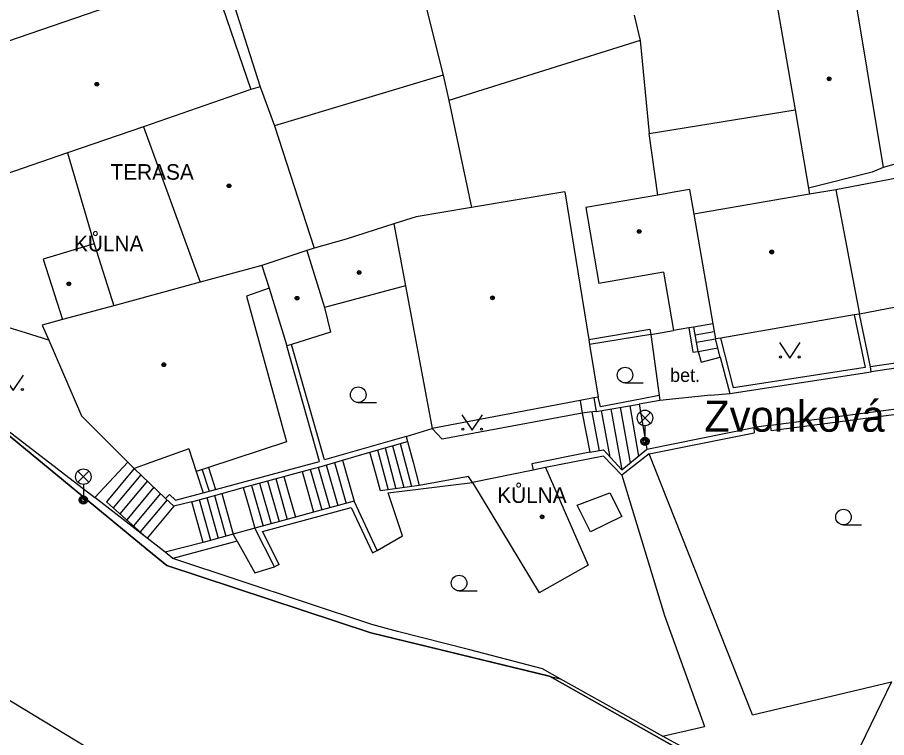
# Model space of a CAD drawing. Extents: x -598233 to -596890, y -1157848 to -1156431.
# Drawn here: x -597276.5 to -597234.6, y -1157601.12 to -1157566.43 of the extents above; entities that cross this region are included whole.
import ezdxf

# ---------------------------------------------------------------- set-up
doc = ezdxf.new("R2010")
doc.units = 0
for name, color, linetype in [('Level 1', 7, 'Continuous'), ('Level 11', 7, 'Continuous'), ('Level 33', 7, 'Continuous'), ('Level 36', 7, 'Continuous'), ('Level 39', 7, 'Continuous'), ('Level 40', 7, 'Continuous'), ('Level 41', 7, 'Continuous'), ('Level 49', 7, 'Continuous'), ('Level 5', 7, 'Continuous'), ('Level 51', 7, 'Continuous'), ('Level 7', 7, 'Continuous'), ('Level 8', 7, 'Continuous'), ('Vrstva 54', 7, 'Continuous'), ('Vrstva 60', 7, 'Continuous')]:
    doc.layers.add(name, color=color, linetype=linetype)

msp = doc.modelspace()

# ---------------------------------------------------------------- linework, layer by layer
at = {"layer": 'Level 1'}
msp.add_lwpolyline([(-597502.5, -1157453.93), (-597467.58, -1157472.78), (-597426.75, -1157494.36), (-597424.47, -1157501.56), (-597423.3, -1157502.37), (-597417.06, -1157506.7), (-597411.67, -1157510.44), (-597409.97, -1157511.62), (-597401.88, -1157508.83), (-597373.87, -1157526.16), (-597366.75, -1157525.36), (-597335.98, -1157542.67), (-597325.9, -1157551.23), (-597302.56, -1157566.5), (-597285.2, -1157579.74), (-597269.3, -1157592.83), (-597259.47, -1157596.07), (-597250.34, -1157598.3)], dxfattribs=at)
msp.add_lwpolyline([(-597502.5, -1157453.93), (-597467.58, -1157472.78), (-597426.75, -1157494.36), (-597424.47, -1157501.56), (-597423.3, -1157502.37), (-597417.06, -1157506.7), (-597411.67, -1157510.44), (-597409.97, -1157511.62), (-597401.88, -1157508.83), (-597373.87, -1157526.16), (-597366.75, -1157525.36), (-597335.98, -1157542.67), (-597325.9, -1157551.23), (-597302.56, -1157566.5), (-597285.2, -1157579.74), (-597269.3, -1157592.83), (-597259.47, -1157596.07), (-597250.34, -1157598.3)], dxfattribs=at)
at = {"layer": 'Level 11'}
for points in [[(-597058.24, -1157731.86), (-597398.31, -1157525.73)], [(-597246.48, -1157567.54), (-597246.04, -1157572.02)], [(-597255.71, -1157570.44), (-597254.61, -1157575.59)], [(-597245.63, -1157574.99), (-597246.04, -1157572.02), (-597239.01, -1157570.89)], [(-597274.09, -1157572.96), (-597272.8, -1157577.34)], [(-597243.83, -1157581.7199), (-597242.9099, -1157581.56)], [(-597243.77, -1157582.08), (-597242.85, -1157581.92)], [(-597243.69, -1157582.52), (-597242.74, -1157582.35)], [(-597243.69, -1157582.52), (-597243.54, -1157583.04), (-597242.62, -1157582.8)], [(-597249.38, -1157584.88), (-597249.27, -1157585.49)], [(-597246.53, -1157585.06), (-597246.1599, -1157587.23)], [(-597248.6, -1157585.4099), (-597248.92, -1157585.45), (-597249.27, -1157585.49)], [(-597248.81, -1157585.44), (-597248.45, -1157587.31)], [(-597248.36, -1157585.37), (-597247.94, -1157587.62)], [(-597247.9, -1157585.29), (-597247.37, -1157588.23)], [(-597247.44, -1157585.21), (-597246.96, -1157587.89)], [(-597246.98, -1157585.14), (-597246.56, -1157587.56)], [(-597249.27, -1157585.49), (-597256.03, -1157586.75), (-597256.5, -1157586.23)], [(-597249.27, -1157585.49), (-597248.9, -1157587.38)], [(-597258.42, -1157587.07), (-597257.88, -1157589.08)], [(-597258.05, -1157586.96), (-597257.5, -1157589.03)], [(-597257.69, -1157586.86), (-597257.42, -1157587.86), (-597257.13, -1157588.98)], [(-597257.13, -1157588.98), (-597259, -1157589.24), (-597259.24, -1157588.36), (-597259.51, -1157587.38)], [(-597259.14, -1157587.27), (-597258.63, -1157589.19)], [(-597258.78, -1157587.17), (-597258.25, -1157589.14)], [(-597272.76, -1157589.56), (-597271.17, -1157587.86)], [(-597261.61, -1157587.98), (-597261.05, -1157589.95)], [(-597261.2199, -1157587.87), (-597260.6599, -1157589.85)], [(-597260.83, -1157587.76), (-597260.56, -1157588.73), (-597260.27, -1157589.74)], [(-597270.87, -1157588.1599), (-597272.21, -1157589.76), (-597272.02, -1157589.92)], [(-597270.87, -1157588.1599), (-597269.36, -1157589.6)], [(-597267.88, -1157588.31), (-597267.55, -1157589.33)], [(-597267.59, -1157588.2199), (-597267.25, -1157589.25)], [(-597267.29, -1157588.12), (-597266.95, -1157589.17)], [(-597262.78, -1157588.31), (-597262.5, -1157589.27), (-597262.2199, -1157590.27)], [(-597262.39, -1157588.2), (-597261.83, -1157590.1599)], [(-597262, -1157588.09), (-597261.44, -1157590.06)], [(-597270.55, -1157588.46), (-597271.88, -1157590.05)], [(-597270.23, -1157588.76), (-597271.56, -1157590.34)], [(-597264.44, -1157588.76), (-597263.88, -1157590.7199)], [(-597264.04, -1157588.65), (-597263.49, -1157590.62)], [(-597263.65, -1157588.55), (-597263.38, -1157589.51), (-597263.1, -1157590.51)], [(-597254.56, -1157588.84), (-597254.75, -1157588.54), (-597257.13, -1157588.98)], [(-597269.92, -1157589.06), (-597271.23, -1157590.63)], [(-597265.61, -1157589.08), (-597265.33, -1157590.05), (-597265.05, -1157591.04)], [(-597265.2199, -1157588.98), (-597264.6599, -1157590.94)], [(-597264.83, -1157588.87), (-597264.27, -1157590.83)], [(-597269.6, -1157589.37), (-597270.9, -1157590.92)], [(-597269.28, -1157589.67), (-597270.58, -1157591.2199)], [(-597267.73, -1157589.6599), (-597267.19, -1157591.62)], [(-597267.37, -1157589.56), (-597266.82, -1157591.52)], [(-597267, -1157589.46), (-597266.46, -1157591.42)], [(-597266.64, -1157589.36), (-597266.37, -1157590.34), (-597266.1, -1157591.32)], [(-597249.51, -1157589.93), (-597247.94, -1157589.34), (-597247.37, -1157590.48), (-597248.87, -1157591.2199), (-597249.51, -1157589.93)], [(-597272.02, -1157589.92), (-597270.25, -1157591.51)], [(-597268.96, -1157589.9699), (-597270.25, -1157591.51)], [(-597267.55, -1157591.7199), (-597267.82, -1157590.74), (-597268.09, -1157589.76)], [(-597265.05, -1157591.04), (-597266.1, -1157591.32)], [(-597265.9099, -1157591.6599), (-597265.06, -1157593.19), (-597264.11, -1157592.9)], [(-597234.37, -1157598.44), (-597237.86, -1157605.63)]]:
    msp.add_lwpolyline(points, dxfattribs=at)
at = {"layer": 'Level 33'}
for p, q in [((-597246.515, -1157585.99), (-597245.985, -1157585.46)), ((-597246.515, -1157585.46), (-597245.985, -1157585.99)), ((-597246.25, -1157586.1), (-597246.25, -1157586.85)), ((-597273.585, -1157588.82), (-597273.055, -1157588.29)), ((-597273.585, -1157588.29), (-597273.055, -1157588.82)), ((-597273.32, -1157588.93), (-597273.32, -1157589.68))]:
    msp.add_line(p, q, dxfattribs=at)
for centre, radius in [((-597246.25, -1157585.725), 0.375), ((-597246.25, -1157586.85), 0.2), ((-597246.25, -1157586.85), 0.1445), ((-597246.25, -1157586.85), 0.0876), ((-597273.32, -1157588.555), 0.375), ((-597273.32, -1157589.68), 0.2), ((-597273.32, -1157589.68), 0.1445), ((-597273.32, -1157589.68), 0.0876)]:
    msp.add_circle(centre, radius, dxfattribs=at)
at = {"layer": 'Level 36'}
for p, q in [((-597247.21, -1157584.0349), (-597246.335, -1157584.0349)), ((-597260.07, -1157584.985), (-597259.195, -1157584.985)), ((-597236.68, -1157590.875), (-597235.805, -1157590.875)), ((-597255.21, -1157594.055), (-597254.335, -1157594.055))]:
    msp.add_line(p, q, dxfattribs=at)
for points in [[(-597239.77, -1157582.09), (-597239.27, -1157582.84), (-597238.77, -1157582.09)], [(-597277.21, -1157583.6599), (-597276.71, -1157584.4099), (-597276.21, -1157583.6599)], [(-597255.08, -1157585.57), (-597254.58, -1157586.32), (-597254.08, -1157585.57)]]:
    msp.add_lwpolyline(points, dxfattribs=at)
for centre, radius in [((-597239.7202, -1157582.7898), 0.05), ((-597238.8208, -1157582.7898), 0.05), ((-597247.2101, -1157583.6598), 0.375), ((-597276.2608, -1157584.3597), 0.05), ((-597260.0701, -1157584.6099), 0.375), ((-597255.0302, -1157586.2698), 0.05), ((-597254.1308, -1157586.2698), 0.05), ((-597236.6801, -1157590.4999), 0.375), ((-597255.2101, -1157593.6799), 0.375)]:
    msp.add_circle(centre, radius, dxfattribs=at)
at = {"layer": 'Level 39'}
for centre, radius in [((-597272.67, -1157569.65), 0.09), ((-597237.37, -1157569.39), 0.09), ((-597237.37, -1157569.39), 0.0398), ((-597272.67, -1157569.65), 0.0398), ((-597266.3, -1157574.54), 0.09), ((-597266.3, -1157574.54), 0.0398), ((-597246.53, -1157576.74), 0.09), ((-597246.53, -1157576.74), 0.0398), ((-597240.14, -1157577.73), 0.09), ((-597240.14, -1157577.73), 0.0398), ((-597260.03, -1157578.7199), 0.09), ((-597260.03, -1157578.7199), 0.0398), ((-597274.02, -1157579.27), 0.09), ((-597274.02, -1157579.27), 0.0398), ((-597263.02, -1157579.96), 0.09), ((-597263.02, -1157579.96), 0.0398), ((-597253.6, -1157579.94), 0.09), ((-597253.6, -1157579.94), 0.0398), ((-597269.44, -1157583.1599), 0.09), ((-597269.44, -1157583.1599), 0.0398), ((-597251.21, -1157590.49), 0.09), ((-597251.21, -1157590.49), 0.0398)]:
    msp.add_circle(centre, radius, dxfattribs=at)
at = {"layer": 'Level 5'}
for points in [[(-597258.04, -1157560.99), (-597255.9699, -1157569.21)], [(-597266.6599, -1157563.93), (-597264.8, -1157569.77)], [(-597267.19, -1157564.2199), (-597280.84, -1157568.9099)], [(-597267.19, -1157564.2199), (-597265.24, -1157569.9)], [(-597236.35, -1157564.17), (-597234.76, -1157573.6599)], [(-597240.03, -1157564.94), (-597239.01, -1157570.89), (-597238.32, -1157574.95)], [(-597246.77, -1157566.33), (-597246.48, -1157567.54)], [(-597246.48, -1157567.54), (-597255.71, -1157570.44)], [(-597255.9699, -1157569.21), (-597264.11, -1157571.6599)], [(-597255.9699, -1157569.21), (-597255.71, -1157570.44)], [(-597265.24, -1157569.9), (-597270.42, -1157571.7)], [(-597264.8, -1157569.77), (-597265.24, -1157569.9)], [(-597264.8, -1157569.77), (-597264.11, -1157571.6599)], [(-597270.42, -1157571.7), (-597274.09, -1157572.96)], [(-597270.42, -1157571.7), (-597267.69, -1157579.19)], [(-597264.11, -1157571.6599), (-597262.2, -1157577.55)], [(-597228.2199, -1157571.81), (-597234.76, -1157573.6599)], [(-597274.09, -1157572.96), (-597278.79, -1157574.57)], [(-597227.99, -1157573), (-597237.05, -1157574.73)], [(-597234.76, -1157573.6599), (-597235.3, -1157573.88)], [(-597235.3, -1157573.88), (-597238.37, -1157574.65)], [(-597250.11, -1157574.83), (-597254.61, -1157575.59)], [(-597250.11, -1157574.83), (-597248.96, -1157581.94)], [(-597244.76, -1157574.84), (-597245.63, -1157574.99), (-597249.1, -1157575.59)], [(-597244.1, -1157574.7199), (-597244.76, -1157574.84)], [(-597244.1, -1157574.7199), (-597243.89, -1157575.9099)], [(-597237.05, -1157574.73), (-597238.32, -1157574.95), (-597243.89, -1157575.9099)], [(-597237.05, -1157574.73), (-597235.9099, -1157580.7199)], [(-597254.61, -1157575.59), (-597257.28, -1157576.04)], [(-597249.1, -1157575.59), (-597248.4699, -1157579.25)], [(-597257.28, -1157576.04), (-597258.35, -1157576.38)], [(-597243.89, -1157575.9099), (-597242.98, -1157581.19)], [(-597258.35, -1157576.38), (-597260.65, -1157577.11)], [(-597258.35, -1157576.38), (-597257.79, -1157579.36)], [(-597272.8, -1157577.34), (-597275.25, -1157578.08)], [(-597272.8, -1157577.34), (-597271.85, -1157580.32)], [(-597260.65, -1157577.11), (-597262.2, -1157577.55)], [(-597262.54, -1157577.6599), (-597264.71, -1157578.39)], [(-597262.2, -1157577.55), (-597262.54, -1157577.6599)], [(-597262.54, -1157577.6599), (-597261.69, -1157580.4)], [(-597275.25, -1157578.08), (-597274.32, -1157580.98)], [(-597264.71, -1157578.39), (-597267.69, -1157579.19)], [(-597264.71, -1157578.39), (-597264.36, -1157579.4699)], [(-597245.35, -1157578.71), (-597248.4699, -1157579.25)], [(-597245.35, -1157578.71), (-597244.87, -1157581.52)], [(-597267.69, -1157579.19), (-597271.85, -1157580.32)], [(-597264.36, -1157579.4699), (-597265.46, -1157579.86)], [(-597264.36, -1157579.4699), (-597263.51, -1157582.25)], [(-597257.79, -1157579.36), (-597261.69, -1157580.4)], [(-597257.79, -1157579.36), (-597256.5, -1157586.23)], [(-597228.9, -1157579.38), (-597235.9099, -1157580.7199)], [(-597265.46, -1157579.86), (-597263.52, -1157586.88)], [(-597271.85, -1157580.32), (-597274.32, -1157580.98)], [(-597261.69, -1157580.4), (-597261.4, -1157581.59)], [(-597236.1599, -1157580.76), (-597242.6, -1157581.88)], [(-597235.9099, -1157580.7199), (-597236.1599, -1157580.76)], [(-597274.32, -1157580.98), (-597275.3, -1157581.25)], [(-597275.3, -1157581.25), (-597274.98, -1157581.98)], [(-597242.98, -1157581.19), (-597243.9, -1157581.35)], [(-597242.98, -1157581.19), (-597242.85, -1157581.92)], [(-597261.4, -1157581.59), (-597263.28, -1157582.18)], [(-597244.14, -1157581.39), (-597244.87, -1157581.52)], [(-597243.9, -1157581.35), (-597244.14, -1157581.39)], [(-597274.98, -1157581.98), (-597273.4099, -1157585.62)], [(-597248.96, -1157581.94), (-597248.92, -1157582.18)], [(-597242.6, -1157581.88), (-597242.85, -1157581.92)], [(-597263.28, -1157582.18), (-597263.51, -1157582.25)], [(-597248.92, -1157582.18), (-597248.51, -1157584.7199)], [(-597249.38, -1157584.88), (-597256.5, -1157586.23)], [(-597248.7199, -1157584.76), (-597249.38, -1157584.88)], [(-597248.51, -1157584.7199), (-597248.7199, -1157584.76)], [(-597273.4099, -1157585.62), (-597271.17, -1157587.86)], [(-597263.52, -1157586.88), (-597267.29, -1157588.12)], [(-597268.24, -1157587.2199), (-597270.87, -1157588.1599)], [(-597268.24, -1157587.2199), (-597267.88, -1157588.31)], [(-597271.17, -1157587.86), (-597270.87, -1157588.1599)], [(-597267.29, -1157588.12), (-597267.88, -1157588.31)], [(-597251.64, -1157588.24), (-597254.56, -1157588.84)], [(-597251.05, -1157588.12), (-597251.64, -1157588.24)], [(-597251.05, -1157588.12), (-597248.98, -1157592.82)], [(-597254.56, -1157588.84), (-597251.35, -1157594.15)], [(-597248.98, -1157592.82), (-597251.35, -1157594.15)]]:
    msp.add_lwpolyline(points, dxfattribs=at)
at = {"layer": 'Level 51'}
for points in [[(-597287.7199, -1157578.06), (-597272.76, -1157589.56)], [(-597287.7199, -1157578.06), (-597272.76, -1157589.56)], [(-597270.25, -1157591.51), (-597272.76, -1157589.56)], [(-597269.38, -1157592.19), (-597270.25, -1157591.51)], [(-597269.01, -1157592.49), (-597269.38, -1157592.19)]]:
    msp.add_lwpolyline(points, dxfattribs=at)
at = {"layer": 'Level 7'}
for points in [[(-597274.98, -1157581.98), (-597276.11, -1157581.63), (-597279.05, -1157580.7199), (-597280.58, -1157579.49)], [(-597236.1599, -1157580.76), (-597235.64, -1157583.3), (-597241.98, -1157584.27), (-597242.6, -1157581.88)], [(-597235.38, -1157583.26), (-597235.9099, -1157580.7199)], [(-597248.96, -1157581.94), (-597246.01, -1157581.45), (-597245.9699, -1157581.7)], [(-597245.9699, -1157581.7), (-597248.92, -1157582.18)], [(-597245.9699, -1157581.7), (-597245.56, -1157584.64)], [(-597244.14, -1157581.39), (-597243.94, -1157582.56), (-597243.69, -1157582.52)], [(-597243.69, -1157582.52), (-597243.9, -1157581.35)], [(-597242.62, -1157582.8), (-597242.85, -1157581.92)], [(-597261.93, -1157587.82), (-597263.51, -1157582.25)], [(-597257.76, -1157586.62), (-597261.69, -1157587.75), (-597263.28, -1157582.18)], [(-597228.35, -1157582.21), (-597234.17, -1157583.08), (-597235.38, -1157583.26)], [(-597228.31, -1157582.46), (-597235.34, -1157583.51)], [(-597242.62, -1157582.8), (-597242.1599, -1157584.55)], [(-597235.34, -1157583.51), (-597235.38, -1157583.26)], [(-597242.1599, -1157584.55), (-597235.34, -1157583.51)], [(-597245.56, -1157584.64), (-597246.39, -1157584.81), (-597248.39, -1157585.19), (-597248.51, -1157584.7199)], [(-597245.56, -1157584.64), (-597245.53, -1157584.89)], [(-597243.08, -1157584.63), (-597245.53, -1157584.89)], [(-597240.19, -1157586.08), (-597227.74, -1157584.45)], [(-597248.7199, -1157584.76), (-597248.6, -1157585.4099)], [(-597248.6, -1157585.4099), (-597246.53, -1157585.06)], [(-597245.53, -1157584.89), (-597246.53, -1157585.06)], [(-597240.1599, -1157586.33), (-597227.86, -1157584.7199)], [(-597246.1599, -1157587.23), (-597241.01, -1157586.19)], [(-597241.01, -1157586.19), (-597240.98, -1157586.44)], [(-597240.1599, -1157586.33), (-597240.19, -1157586.08)], [(-597257.76, -1157586.62), (-597257.69, -1157586.86)], [(-597246.05, -1157587.46), (-597240.98, -1157586.44)], [(-597259.51, -1157587.38), (-597257.69, -1157586.86)], [(-597260.83, -1157587.76), (-597259.51, -1157587.38)], [(-597248.9, -1157587.38), (-597251.7, -1157587.93), (-597251.64, -1157588.24)], [(-597248.25, -1157587.57), (-597251.05, -1157588.12)], [(-597248.9, -1157587.38), (-597248.25, -1157587.27), (-597247.37, -1157588.23), (-597246.1599, -1157587.23)], [(-597247.36, -1157588.48), (-597248.25, -1157587.57)], [(-597246.05, -1157587.46), (-597247.36, -1157588.48)], [(-597241.07, -1157600.02), (-597246.05, -1157587.46)], [(-597266.95, -1157589.17), (-597262.84, -1157588.07), (-597261.93, -1157587.82)], [(-597262.78, -1157588.31), (-597261.86, -1157588.06), (-597260.83, -1157587.76)], [(-597263.65, -1157588.55), (-597262.78, -1157588.31)], [(-597265.61, -1157589.08), (-597263.65, -1157588.55)], [(-597247.36, -1157588.48), (-597245.3, -1157595.24), (-597243.38, -1157600.59)], [(-597267.55, -1157589.33), (-597266.95, -1157589.17)], [(-597266.64, -1157589.36), (-597265.61, -1157589.08)], [(-597259.1599, -1157592.11), (-597257.93, -1157591.4099), (-597258.63, -1157589.33), (-597254.56, -1157588.84)], [(-597269.36, -1157589.6), (-597269.1599, -1157589.4099), (-597268.88, -1157589.69), (-597267.55, -1157589.33)], [(-597268.96, -1157589.9699), (-597269.36, -1157589.6)], [(-597268.09, -1157589.76), (-597266.64, -1157589.36)], [(-597268.09, -1157589.76), (-597268.96, -1157589.9699)], [(-597263.88, -1157592.79), (-597264.69, -1157591.2), (-597260.4099, -1157590.04), (-597259.39, -1157592.2199)], [(-597260.27, -1157589.74), (-597262.2199, -1157590.27)], [(-597259.1599, -1157592.11), (-597260.27, -1157589.74)], [(-597262.2199, -1157590.27), (-597263.1, -1157590.51)], [(-597263.1, -1157590.51), (-597265.05, -1157591.04)], [(-597266.1, -1157591.32), (-597267.55, -1157591.7199)], [(-597265.9099, -1157591.6599), (-597266.1, -1157591.32)], [(-597264.11, -1157592.9), (-597265.05, -1157591.04)], [(-597267.55, -1157591.7199), (-597269.38, -1157592.19)], [(-597265.9099, -1157591.6599), (-597269.01, -1157592.49)], [(-597259.39, -1157592.2199), (-597259.1599, -1157592.11)], [(-597245.4, -1157601.05), (-597247.58, -1157599.83), (-597250.34, -1157598.3), (-597251.19, -1157597.82), (-597254.69, -1157596.9), (-597258.17, -1157596.01), (-597259.42, -1157595.67), (-597269.01, -1157592.49)], [(-597263.88, -1157592.79), (-597264.11, -1157592.9)], [(-597241.07, -1157600.02), (-597234.37, -1157598.44)], [(-597245.4, -1157601.05), (-597243.38, -1157600.59)], [(-597237.86, -1157605.63), (-597240.32, -1157603.81), (-597245.4, -1157601.05)]]:
    msp.add_lwpolyline(points, dxfattribs=at)
at = {"layer": 'Level 8'}
for points in [[(-597245.9699, -1157581.7), (-597244.87, -1157581.52)], [(-597243.08, -1157584.63), (-597242.1599, -1157584.55)], [(-597257.76, -1157586.62), (-597256.5, -1157586.23)], [(-597240.19, -1157586.08), (-597241.01, -1157586.19)]]:
    msp.add_lwpolyline(points, dxfattribs=at)
at = {"layer": 'Vrstva 54'}
for p, q in [((-597285.2, -1157579.74), (-597270.24, -1157592.06)), ((-597270.24, -1157592.06), (-597269.3, -1157592.83)), ((-597269.3, -1157592.83), (-597259.47, -1157596.07)), ((-597259.47, -1157596.07), (-597250.85, -1157598.17)), ((-597250.85, -1157598.17), (-597245.81, -1157601.01)), ((-597245.81, -1157601.01), (-597239.94, -1157604.31))]:
    msp.add_line(p, q, dxfattribs=at)
at = {"layer": 'Vrstva 60'}
for points in [[(-597366.75, -1157525.36), (-597335.98, -1157542.67), (-597325.9, -1157551.23), (-597302.56, -1157566.5), (-597285.2, -1157579.74), (-597270.24, -1157592.06), (-597269.3, -1157592.83), (-597259.47, -1157596.07), (-597250.85, -1157598.17), (-597245.81, -1157601.01), (-597239.94, -1157604.31), (-597223.03, -1157616.87), (-597206.27, -1157628.35), (-597179.87, -1157644.26)], [(-597179.87, -1157644.26), (-597206.27, -1157628.35), (-597223.03, -1157616.87), (-597239.94, -1157604.31), (-597245.81, -1157601.01), (-597250.85, -1157598.17), (-597259.47, -1157596.07), (-597269.3, -1157592.83), (-597270.24, -1157592.06), (-597285.2, -1157579.74), (-597302.56, -1157566.5), (-597325.9, -1157551.23), (-597335.98, -1157542.67), (-597366.75, -1157525.36)]]:
    msp.add_lwpolyline(points, dxfattribs=at)

# ---------------------------------------------------------------- texts
at = {"layer": 'Level 40'}
msp.add_text('bet.', height=0.65, dxfattribs=at).set_placement((-597245.04, -1157583.99))
at = {"layer": 'Level 41'}
for s, p in [('TERASA', (-597272.01, -1157574.25)), ('KŮLNA', (-597273.77, -1157577.7)), ('KŮLNA', (-597253.37, -1157589.82))]:
    msp.add_text(s, height=0.75, dxfattribs=at).set_placement(p)
at = {"layer": 'Level 49'}
msp.add_text('Zvonková', height=1.5, dxfattribs=at).set_placement((-597243.39, -1157586.39))

doc.saveas('drawing.dxf')
